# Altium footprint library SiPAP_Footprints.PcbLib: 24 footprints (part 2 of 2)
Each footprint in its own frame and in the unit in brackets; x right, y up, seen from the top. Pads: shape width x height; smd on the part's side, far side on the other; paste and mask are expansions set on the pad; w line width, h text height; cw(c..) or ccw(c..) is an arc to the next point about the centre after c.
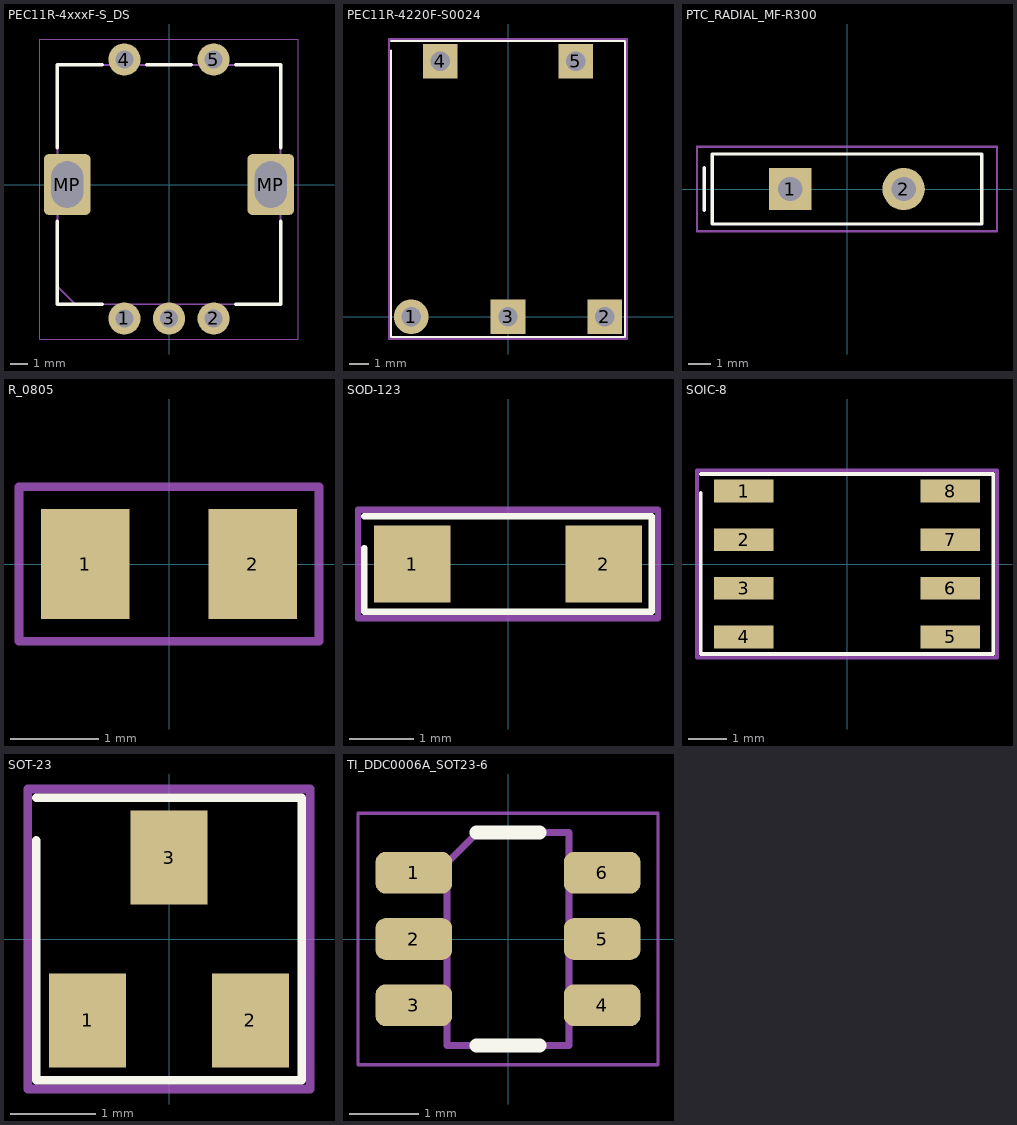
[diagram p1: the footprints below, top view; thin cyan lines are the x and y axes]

## PEC11R-4xxxF-S_DS [mm] "Custom, 6 pads; custom lands, density N (nominal); from Bourns PEC11R Series 12 mm Incremental Encoder datasheet, PEC11R-4xxxF-Sxxxx recommended PCB layout, p. 2; Bourns PEC11R-4xxxF-Sxxxx PCB layout (datasheet p2). Origin = shaft centre. A-C-B 2.5mm pitch 7.5mm below, switch pins 7.0mm above, 2 plated mounting slots 1.8x2.6 (13.2 outer), pad MP = mechanical."
height 31.5
pads (7):
  round 1.8 hole 1: 1(-2.5,-7.5) 2(2.5,-7.5) 3(0,-7.5) 4(-2.5,7) 5(2.5,7)
  rrect19% 2.6x3.4 hole 1.8 slot 2.6 at 90 deg: MP(-5.7,0) MP(5.7,0)
Top Overlay:
  lines w0.2: -6.25,-2.05 -6.25,-6.7 -3.75,-6.7 ; -6.25,2.05 -6.25,6.7 -3.75,6.7 ; -1.25,6.7 1.25,6.7 ; 3.75,-6.7 6.25,-6.7 6.25,-2.05 ; 3.75,6.7 6.25,6.7 6.25,2.05
Mechanical 13:
  lines w0.1: -6.25,-5.7 -5.25,-6.7 6.25,-6.7 6.25,6.7 -6.25,6.7 -6.25,-5.7
  text ".Designator" at -5.075,-0.5 h1
Mechanical 15:
  lines w0.05: -7.25,-8.65 7.25,-8.65 7.25,8.15 -7.25,8.15 -7.25,-8.65
3D body: height 6.5, standoff 0, extent -6.25,-6.7 6.25,6.7
3D body: height 13.5, standoff 6.5, extent -3.5,-3.5 3.5,3.5
3D body: height 31.5, standoff 13.5, extent -3,-3 3,3

## PEC11R-4220F-S0024 [mm] "Bourns PEC11R-4xxxF-Sxxxx bottom view pad layout (Rev 04/26): A-C-B row 5mm pitch, switch pins 13.2mm offset, 7mm apart"
pads (5):
  round 1.8 smd: 1(-5,0)
  rect 1.8x1.8 smd: 2(5,0) 3(0,0) 4(-3.5,13.2) 5(3.5,13.2)
Top Overlay:
  lines w0.1: -6.05,13.75 -6.05,-1.05 6.05,-1.05 6.05,14.25 -6.05,14.25
Mechanical 15:
  lines w0.1: -6.15,-1.15 -6.15,14.35 6.15,14.35 6.15,-1.15 -6.15,-1.15

## PTC_RADIAL_MF-R300 [mm] "Bourns MF-R300 radial PPTC (datasheet p3: A 12.0 max, B 18.3 max tall, C 5.1 lead spacing, E 3.0 max, lead dia 0.81). Hole 1.1 mm."
pads (2):
  rect 1.905x1.905 hole 1.1: 1(-2.55,0)
  round 1.905 hole 1.1: 2(2.55,0)
Top Overlay:
  lines w0.152: -6.426,-0.953 -6.426,0.953 ; -6.071,-1.575 6.071,-1.575 6.071,1.575 -6.071,1.575 -6.071,-1.575
Mechanical 1:
  lines w0.102: -6.756,-1.905 6.756,-1.905 6.756,1.905 -6.756,1.905 -6.756,-1.905
3D body: height 24.8, standoff 0, extent -7.2,-1.5 7.2,1.5

## R_0805 [mm] "Standard 0805 SMD chip resistor land pattern (IPC nominal)"
pads (2):
  rect 1x1.25 smd: 1(-0.95,0) 2(0.95,0)
Mechanical 15:
  lines w0.1: -1.7,-0.875 -1.7,0.875 1.7,0.875 1.7,-0.875 -1.7,-0.875
3D body: height 1.25, standoff 0, extent -1,-0.625 1,0.625

## SOD-123 [mm] "Standard SOD-123 diode package, 2-pin (D1 reverse polarity protect)"
pads (2):
  rect 1.2x1.2 smd: 1(-1.5,0) 2(1.5,0)
Top Overlay:
  lines w0.1: -2.25,0.25 -2.25,-0.75 2.25,-0.75 2.25,0.75 -2.25,0.75
Mechanical 15:
  lines w0.1: -2.35,-0.85 -2.35,0.85 2.35,0.85 2.35,-0.85 -2.35,-0.85

## SOIC-8 [mm] "Standard SOIC-8, 1.27mm pitch, 3.9mm body (LM393 comparator)"
pads (8):
  rect 1.55x0.6 smd: 1(-2.7,1.905) 2(-2.7,0.635) 3(-2.7,-0.635) 4(-2.7,-1.905) 5(2.7,-1.905) 6(2.7,-0.635) 7(2.7,0.635) 8(2.7,1.905)
Top Overlay:
  lines w0.1: -3.825,1.855 -3.825,-2.355 3.825,-2.355 3.825,2.355 -3.825,2.355
Mechanical 15:
  lines w0.1: -3.925,-2.455 -3.925,2.455 3.925,2.455 3.925,-2.455 -3.925,-2.455
3D body: height 1.75, standoff 0, extent -1.95,-2.45 1.95,2.45
3D body: height 0.4, standoff 0, extent -3,-2.2 3,2.2

## SOT-23 [mm] "Standard SOT-23-3, 0.95mm pitch (AO3401A P-MOSFET, pin1=G pin2=S pin3=D)"
pads (3):
  rect 0.9x1.1 smd: 1(-0.95,-0.95) 2(0.95,-0.95) 3(0,0.95)
Top Overlay:
  lines w0.1: -1.55,1.15 -1.55,-1.65 1.55,-1.65 1.55,1.65 -1.55,1.65
Mechanical 15:
  lines w0.1: -1.65,-1.75 -1.65,1.75 1.65,1.75 1.65,-1.75 -1.65,-1.75
3D body: height 1.12, standoff 0, extent -1.45,-0.65 1.45,0.65

## TI_DDC0006A_SOT23-6 [mm] "Custom, 6 pads; custom lands, density N (nominal); from TI TPS54202 datasheet SLVSD26C, C (Feb 2026), DDC0006A Example Board Layout, p. 29; TI DDC0006A (SOT-23-6, 1.1 max height) land pattern per TPS54202 datasheet p29."
height 1.1
pads (6):
  rrect50% 1.1x0.6 smd: 1(-1.35,0.95) 2(-1.35,0) 3(-1.35,-0.95) 4(1.35,-0.95) 5(1.35,0) 6(1.35,0.95)
Top Overlay:
  lines w0.2: -0.45,-1.525 0.45,-1.525 ; -0.45,1.525 0.45,1.525
Mechanical 13:
  lines w0.1: -0.875,-1.525 0.875,-1.525 0.875,1.525 -0.437,1.525 -0.875,1.088 -0.875,-1.525
  text ".Designator" at -1.522,-0.15 h0.3
Mechanical 15:
  lines w0.05: -2.15,-1.8 2.15,-1.8 2.15,1.8 -2.15,1.8 -2.15,-1.8
3D body: height 1.1, standoff 0, extent -0.8,-1.45 0.8,1.45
